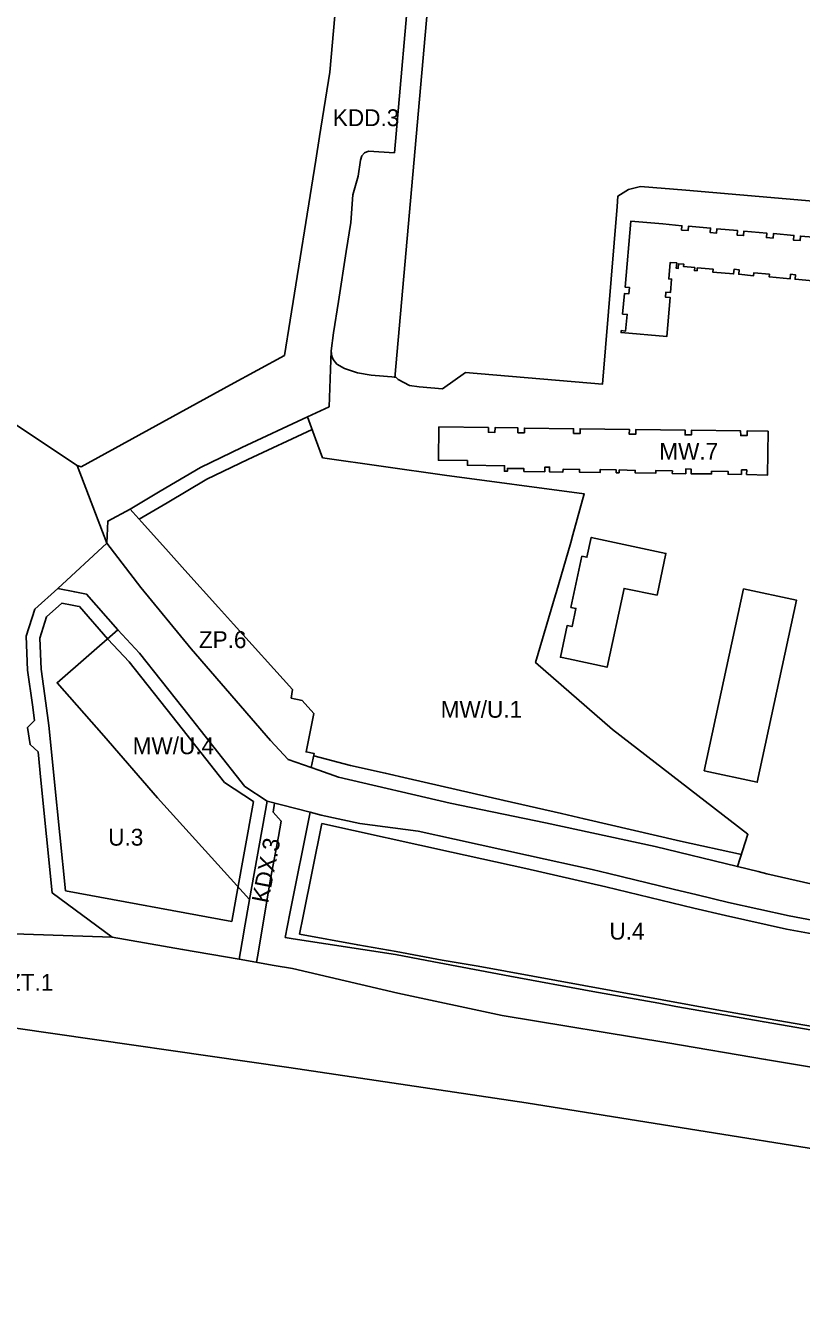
# Model space of a CAD drawing. Extents: x 7427060 to 7429122, y 5545301 to 5546237.
# Drawn here: x 7427783.1 to 7428012.9, y 5545328.8 to 5545710.8 of the extents above; entities that cross this region are included whole.
import ezdxf

# ---------------------------------------------------------------- set-up
doc = ezdxf.new("R2010")
doc.units = 0
for name, color, linetype in [('LIN_Linia Zabudowy Nieprzekraczalna', 7, 'Continuous'), ('LIN_Linia Zabudowy Obowiązujaca', 7, 'Continuous'), ('LIN_Linie Rozgraniczajace', 7, 'Continuous'), ('TXT_Oznaczenia Przeznaczenia', 7, 'Continuous')]:
    doc.layers.add(name, color=color, linetype=linetype)

msp = doc.modelspace()

# ---------------------------------------------------------------- linework, layer by layer
at = {"layer": 'LIN_Linia Zabudowy Nieprzekraczalna'}
for p, q in [((7427796.86, 5545539.15), (7427793.76, 5545539.76)), ((7427798.34, 5545538.86), (7427796.86, 5545539.15)), ((7427799.02, 5545538.73), (7427798.34, 5545538.86)), ((7427807.39, 5545529.13), (7427799.02, 5545538.73)), ((7427813.77, 5545522.35), (7427807.39, 5545529.13)), ((7427826.48, 5545506.29), (7427813.77, 5545522.35)), ((7427842.04, 5545486.59), (7427826.48, 5545506.29)), ((7427850.61, 5545480.97), (7427842.04, 5545486.59)), ((7427909.31, 5545465.94), (7427870.83, 5545474.45)), ((7427931.26, 5545461.1), (7427909.31, 5545465.94)), ((7427955.02, 5545455.73), (7427931.26, 5545461.1)), ((7427981.09, 5545449.43), (7427955.02, 5545455.73)), ((7427990.46, 5545447.17), (7427981.09, 5545449.43)), ((7428008.54, 5545443.17), (7427990.46, 5545447.17)), ((7428028.24, 5545439.5), (7428008.54, 5545443.17))]:
    msp.add_line(p, q, dxfattribs=at)
for points in [[(7428245.15, 5545897.99), (7428161.59, 5545904.67), (7428139.66, 5545906.42), (7428026.47, 5545915.47), (7427978.93, 5545906.35), (7427970.86, 5545904.87), (7427949.14, 5545903.31), (7427927.98, 5545847.56), (7427923.31, 5545834.83), (7427920.46, 5545827.63), (7427909.28, 5545797.22), (7427905.07, 5545749.44), (7427892.52, 5545606.57)], [(7427867.96, 5545591.25), (7427848.87, 5545582.3), (7427836.8, 5545576.47), (7427824.97, 5545569.51), (7427816.73, 5545564.6)], [(7427793.76, 5545539.76), (7427789.24, 5545535.74), (7427787.26, 5545529.4), (7427787.65, 5545520.23), (7427789.06, 5545510.14), (7427789.95, 5545503.54), (7427790.57, 5545497.65), (7427791.56, 5545487.72), (7427794.89, 5545454.5)], [(7427868.45, 5545494.5), (7427879.36, 5545491.68), (7427889.64, 5545489.39), (7427896.45, 5545487.8), (7427910.64, 5545484.56), (7427924.86, 5545481.28), (7427941.88, 5545477.39), (7427948.54, 5545475.84), (7427977.14, 5545469.27), (7427995.16, 5545465.26)], [(7427844.21, 5545445.39), (7427845.5, 5545452.66), (7427850.61, 5545480.97)], [(7427870.83, 5545474.45), (7427865.29, 5545446.99), (7427864.22, 5545441.69)]]:
    msp.add_lwpolyline(points, dxfattribs=at)
at = {"layer": 'LIN_Linia Zabudowy Obowiązujaca'}
for points in [[(7428019.16, 5545647.96), (7428012.67, 5545648.53), (7428012.55, 5545647.18), (7428010.6, 5545647.35), (7428010.72, 5545648.7), (7428004.68, 5545649.24), (7428004.56, 5545647.93), (7428002.59, 5545648.1), (7428002.7, 5545649.4), (7427995.92, 5545649.99), (7427995.81, 5545648.67), (7427993.89, 5545648.83), (7427994, 5545650.18), (7427987.91, 5545650.69), (7427987.8, 5545649.39), (7427985.93, 5545649.55), (7427986.04, 5545650.87), (7427979.48, 5545651.43), (7427979.37, 5545650.13), (7427977.46, 5545650.29), (7427977.57, 5545651.61), (7427971.87, 5545652.11), (7427962.4, 5545652.92), (7427960.69, 5545633.43), (7427961.98, 5545633.31), (7427961.81, 5545631.37), (7427960.51, 5545631.49), (7427959.98, 5545625.43), (7427961.33, 5545625.31), (7427960.85, 5545620.39), (7427959.56, 5545620.52), (7427959.52, 5545619.95), (7427973.04, 5545618.75), (7427974.06, 5545630.33), (7427972.72, 5545630.4), (7427972.83, 5545631.92), (7427974.2, 5545631.85), (7427974.51, 5545635.78), (7427973.66, 5545635.85), (7427974.08, 5545640.73), (7427976.01, 5545640.58), (7427975.89, 5545638.99), (7427976.45, 5545638.95), (7427976.56, 5545640.35), (7427978.08, 5545640.24), (7427978.03, 5545639.48), (7427981.34, 5545639.21), (7427981.27, 5545638.32), (7427982.04, 5545638.27), (7427982.11, 5545639.1), (7427986.82, 5545638.69), (7427986.75, 5545637.83), (7427992.87, 5545637.31), (7427993, 5545638.68), (7427994.5, 5545638.53), (7427994.38, 5545637.2), (7427998.77, 5545636.78), (7427998.82, 5545637.62), (7428003.5, 5545637.2), (7428003.43, 5545636.4), (7428009.61, 5545635.84), (7428009.73, 5545637.22), (7428011.21, 5545637.08), (7428011.09, 5545635.74), (7428018.47, 5545635.07)], [(7427794.89, 5545454.5), (7427844.21, 5545445.39)], [(7427864.22, 5545441.69), (7427881.49, 5545438.5), (7427892.83, 5545436.53), (7427906.47, 5545434), (7427917.21, 5545432.18), (7427987.92, 5545419.25), (7428003.13, 5545416.58), (7428046.56, 5545409.04), (7428061.43, 5545406.58), (7428075.93, 5545404.37), (7428104.97, 5545399.32), (7428128.5, 5545395.56)]]:
    msp.add_lwpolyline(points, dxfattribs=at)
for points in [[(7427905.51, 5545591.97), (7427905.38, 5545582.09), (7427914, 5545581.98), (7427913.99, 5545580.6), (7427925, 5545580.46), (7427924.97, 5545578.85), (7427925.58, 5545578.87), (7427925.82, 5545578.84), (7427925.83, 5545579.69), (7427930.74, 5545579.62), (7427930.73, 5545578.77), (7427936.91, 5545578.7), (7427936.93, 5545580.1), (7427938.33, 5545580.08), (7427938.31, 5545578.68), (7427942.3, 5545578.62), (7427942.32, 5545579.46), (7427947.23, 5545579.37), (7427947.22, 5545578.55), (7427953.31, 5545578.47), (7427953.32, 5545579.33), (7427958.1, 5545579.23), (7427958.09, 5545578.4), (7427958.94, 5545578.39), (7427958.96, 5545579.24), (7427963.73, 5545579.08), (7427963.72, 5545578.33), (7427969.8, 5545578.24), (7427969.83, 5545579.08), (7427974.72, 5545578.96), (7427974.71, 5545578.18), (7427978.69, 5545578.12), (7427978.71, 5545579.52), (7427980.27, 5545579.49), (7427980.26, 5545578.09), (7427986.33, 5545578.03), (7427986.34, 5545578.86), (7427991.24, 5545578.8), (7427991.22, 5545577.96), (7427995.2, 5545577.92), (7427995.21, 5545579.25), (7427996.74, 5545579.23), (7427996.72, 5545577.89), (7428002.93, 5545577.73), (7428003.09, 5545590.69), (7427996.87, 5545590.79), (7427996.85, 5545589.39), (7427995, 5545589.41), (7427994.96, 5545590.81), (7427980.38, 5545591), (7427980.35, 5545589.6), (7427978.5, 5545589.62), (7427978.48, 5545591.02), (7427963.89, 5545591.2), (7427963.87, 5545589.79), (7427961.95, 5545589.82), (7427961.97, 5545591.22), (7427947.39, 5545591.42), (7427947.38, 5545590.01), (7427945.44, 5545590.04), (7427945.45, 5545591.43), (7427930.89, 5545591.63), (7427930.86, 5545590.23), (7427928.95, 5545590.26), (7427928.97, 5545591.66), (7427922.16, 5545591.76), (7427922.14, 5545590.36), (7427920.21, 5545590.38), (7427920.23, 5545591.78)], [(7427970.24, 5545542.11), (7427972.83, 5545554.48), (7427950.67, 5545559.22), (7427949.41, 5545553.35), (7427947.9, 5545553.67), (7427944.68, 5545538.51), (7427946.14, 5545538.2), (7427945, 5545532.82), (7427943.53, 5545533.13), (7427941.54, 5545523.74), (7427943.96, 5545523.23), (7427955.38, 5545520.79), (7427960.42, 5545544.14)], [(7427995.85, 5545544.02), (7427984.18, 5545490.11), (7427999.89, 5545486.7), (7428011.48, 5545540.66)]]:
    msp.add_lwpolyline(points, close=True, dxfattribs=at)
at = {"layer": 'LIN_Linie Rozgraniczajace'}
for p, q in [((7427884.63, 5545673.7), (7427892.35, 5545673.17)), ((7427873.6, 5545614.56), (7427873.06, 5545597.9)), ((7427892.82, 5545606.76), (7427893.51, 5545606.03)), ((7427866.56, 5545595.01), (7427873.06, 5545597.9)), ((7427798.29, 5545580.52), (7427807.12, 5545557.58)), ((7427814.84, 5545566.71), (7427814, 5545567.63)), ((7427814.84, 5545566.71), (7427814.84, 5545566.71)), ((7427814.84, 5545566.71), (7427817.51, 5545563.73)), ((7427817.51, 5545563.73), (7427825.43, 5545554.93)), ((7427792.59, 5545544.06), (7427807.12, 5545557.58)), ((7427825.43, 5545554.93), (7427830.28, 5545549.54)), ((7427844.65, 5545533.58), (7427862.13, 5545514.13)), ((7427862.13, 5545514.13), (7427861.75, 5545511.65)), ((7427861.75, 5545511.65), (7427865, 5545510.94)), ((7427865, 5545510.94), (7427868.49, 5545507.05)), ((7427849.44, 5545451.96), (7427854.69, 5545481.07)), ((7427867.42, 5545477.78), (7427861.37, 5545447.78)), ((7427847.85, 5545443), (7427849.44, 5545451.96)), ((7427861.37, 5545447.78), (7427859.93, 5545440.69)), ((7427859.93, 5545440.69), (7427862.35, 5545440.32)), ((7427901.98, 5545433.83), (7427926.56, 5545429.28)), ((7427926.56, 5545429.28), (7427951.13, 5545424.74))]:
    msp.add_line(p, q, dxfattribs=at)
for points in [[(7427914.34, 5545897.9), (7427907.96, 5545875.71), (7427880.6, 5545780.66), (7427873.22, 5545697.05), (7427870.17, 5545678.06), (7427869.04, 5545671.02), (7427861.42, 5545623.63), (7427859.75, 5545613.18)], [(7427892.35, 5545673.17), (7427899.09, 5545749.97), (7427900.08, 5545761.2), (7427900.51, 5545764.03)], [(7427859.75, 5545613.18), (7427843.8, 5545604.43), (7427799.57, 5545580.14), (7427798.29, 5545580.52), (7427718, 5545633.88), (7427707.59, 5545635.27), (7427702.63, 5545636.84), (7427681.7, 5545650.45), (7427668.75, 5545659.22), (7427659.47, 5545665.69), (7427650.65, 5545671.64), (7427640.95, 5545678.24), (7427629.82, 5545685.47), (7427623.88, 5545689.05), (7427619.42, 5545691.96), (7427614.34, 5545695.27), (7427608.92, 5545698.58), (7427591.4, 5545710.45)], [(7427881.56, 5545666.25), (7427882.29, 5545671), (7427882.73, 5545672.28), (7427883.49, 5545673.21), (7427884.63, 5545673.7)], [(7427881.56, 5545666.25), (7427879.98, 5545660.7), (7427879.44, 5545652.59)], [(7427893.51, 5545606.03), (7427896.79, 5545604.25), (7427899.66, 5545603.83), (7427906.63, 5545603.24), (7427913.4, 5545608.09), (7427953.99, 5545604.63), (7427958.35, 5545657.26), (7427958.6, 5545660.36), (7427961.73, 5545662.33), (7427965.32, 5545663.18), (7427978.67, 5545662.14), (7428054.16, 5545655.62), (7428053.66, 5545649.13), (7428052.6, 5545635.68), (7428085.46, 5545633.14), (7428089.64, 5545632.82), (7428092.85, 5545632.57), (7428092.48, 5545629.68), (7428090.62, 5545629.82), (7428090.11, 5545622.67)], [(7427892.82, 5545606.76), (7427885.49, 5545607.3), (7427881.41, 5545608.02), (7427877.53, 5545609.31), (7427875.33, 5545610.55), (7427874.2, 5545611.92), (7427873.83, 5545612.96), (7427873.6, 5545614.56), (7427874.33, 5545619.81), (7427875.83, 5545629.1), (7427878.02, 5545643.93), (7427879.44, 5545652.59)], [(7427855.67, 5545499.03), (7427832.1, 5545526.18), (7427817.23, 5545544.37), (7427807.12, 5545557.58), (7427807.38, 5545564.07), (7427814, 5545567.63), (7427822.93, 5545572.95), (7427834.91, 5545580), (7427847.15, 5545585.91), (7427866.56, 5545595.01)], [(7427945.27, 5545560.02), (7427948.59, 5545572.16), (7427907.23, 5545577.66), (7427871.08, 5545582.86), (7427868.99, 5545588.49), (7427866.56, 5545595.01)], [(7427994.01, 5545461.68), (7427997.09, 5545471.26), (7427956.97, 5545502.31), (7427934.2, 5545522.16), (7427940.11, 5545542.21), (7427940.29, 5545542.84), (7427944.59, 5545557.69), (7427945.27, 5545560.02)], [(7427830.28, 5545549.54), (7427840.24, 5545538.49), (7427844.65, 5545533.58)], [(7427792.59, 5545544.06), (7427785.75, 5545538), (7427783.23, 5545529.93), (7427783.66, 5545519.87), (7427785.1, 5545509.59), (7427785.72, 5545505), (7427783.62, 5545502.96), (7427784.37, 5545497.87), (7427786.74, 5545495.72), (7427787.58, 5545487.32)], [(7427910.17, 5545469.85), (7427899.36, 5545472.24), (7427882.13, 5545474.46), (7427870.67, 5545476.94), (7427867.42, 5545477.78), (7427854.69, 5545481.07), (7427848.07, 5545485.41), (7427829.62, 5545508.77), (7427816.8, 5545524.97), (7427810.36, 5545531.82), (7427801.14, 5545542.39), (7427799.11, 5545542.79), (7427797.62, 5545543.08), (7427792.59, 5545544.06)], [(7427810.36, 5545531.82), (7427792.37, 5545516.18), (7427806.2, 5545500.44), (7427822.16, 5545482.1), (7427849.44, 5545451.96)], [(7427868.49, 5545507.05), (7427866.17, 5545495.67), (7427868.59, 5545495.17), (7427867.73, 5545491.02)], [(7427855.67, 5545499.03), (7427860.84, 5545493.46), (7427867.73, 5545491.02)], [(7427875.8, 5545488.15), (7427869.94, 5545490.23), (7427867.73, 5545491.02)], [(7427808.75, 5545440.81), (7427790.93, 5545453.89), (7427787.58, 5545487.32)], [(7427875.8, 5545488.15), (7427908.91, 5545480.54), (7427937.17, 5545474.62), (7427969.6, 5545467.63), (7427994.01, 5545461.68), (7428000.1, 5545460.2), (7428002.72, 5545459.56), (7428034.43, 5545452.34), (7428051.59, 5545448.3), (7428054.59, 5545447.59), (7428058.78, 5545446.66), (7428068.18, 5545444.56), (7428075.27, 5545442.69), (7428089.91, 5545438.74), (7428099.87, 5545434.57), (7428112.8, 5545428.34), (7428120.06, 5545424.14), (7428137.4, 5545415.49), (7428141.53, 5545412.9), (7428158.05, 5545404.11)], [(7427856.78, 5545480.53), (7427856.45, 5545477.84), (7427858.8, 5545475.18), (7427857.96, 5545470.6)], [(7427867.42, 5545477.78), (7427867.42, 5545477.78)], [(7427857.96, 5545470.6), (7427855.71, 5545458.61), (7427853.21, 5545443.87), (7427851.83, 5545435.48), (7427851.44, 5545433.34)], [(7427991.36, 5545451.07), (7427982.03, 5545453.32), (7427974.95, 5545455.03), (7427955.93, 5545459.63), (7427950.94, 5545460.84), (7427932.13, 5545465), (7427910.17, 5545469.85)], [(7428113.02, 5545413.86), (7428107.39, 5545418.47), (7428099.57, 5545423.01), (7428097.13, 5545424.43), (7428088.88, 5545428.01), (7428076.81, 5545431.79), (7428052.58, 5545438.14), (7428049.54, 5545438.77), (7428034.63, 5545441.86), (7428029.15, 5545443.4), (7428009.34, 5545447.09), (7427991.36, 5545451.07)], [(7428225.77, 5545368.53), (7428196.66, 5545372.94), (7428192.6, 5545373.56), (7428147.37, 5545380.77), (7428143.72, 5545381.35), (7428137.2, 5545382.34), (7428135.59, 5545382.6), (7428126.02, 5545384.18), (7428099.12, 5545388.6), (7428081.24, 5545391.54), (7428078.08, 5545392.06), (7428045.68, 5545397.36), (7428022.45, 5545401.16), (7428002.36, 5545404.57), (7427973.33, 5545409.48), (7427924.3, 5545417.53), (7427893.37, 5545424.24), (7427862.15, 5545431.47), (7427856.74, 5545432.41), (7427846.3, 5545434.24), (7427829.57, 5545437.17), (7427808.75, 5545440.81), (7427744.57, 5545442.93)], [(7427847.85, 5545443), (7427847.62, 5545441.71), (7427846.3, 5545434.24)], [(7427862.35, 5545440.32), (7427892.67, 5545435.63), (7427901.98, 5545433.83)], [(7427951.13, 5545424.74), (7427970.74, 5545421.21), (7427975.72, 5545420.24)], [(7427975.72, 5545420.24), (7428001.9, 5545415.7), (7428025.25, 5545411.66)], [(7427780.19, 5545413.81), (7427861.1, 5545402.15), (7427931.36, 5545391.73), (7428070.75, 5545369.4), (7428321.97, 5545328.77)]]:
    msp.add_lwpolyline(points, dxfattribs=at)

# ---------------------------------------------------------------- texts
at = {"layer": 'TXT_Oznaczenia Przeznaczenia'}
for s, rotation, p in [('KDD.3', 360, (7427874.11, 5545681.1)), ('MW.7', 360, (7427970.85, 5545582.24)), ('U.3', 360, (7427807.54, 5545467.91)), ('KDX.3', 78.9635, (7427854.91, 5545450.65)), ('U.4', 360, (7427956.06, 5545440.07)), ('KDZT.1', 360, (7427768.24, 5545424.9))]:
    msp.add_text(s, height=5, rotation=rotation, dxfattribs=at).set_placement(p)
for s, p in [('ZP.6', (7427834.39, 5545526.44)), ('MW/U.1', (7427906.06, 5545505.81)), ('MW/U.4', (7427814.78, 5545495.01))]:
    msp.add_text(s, height=5, dxfattribs=at).set_placement(p)

doc.saveas('drawing.dxf')
